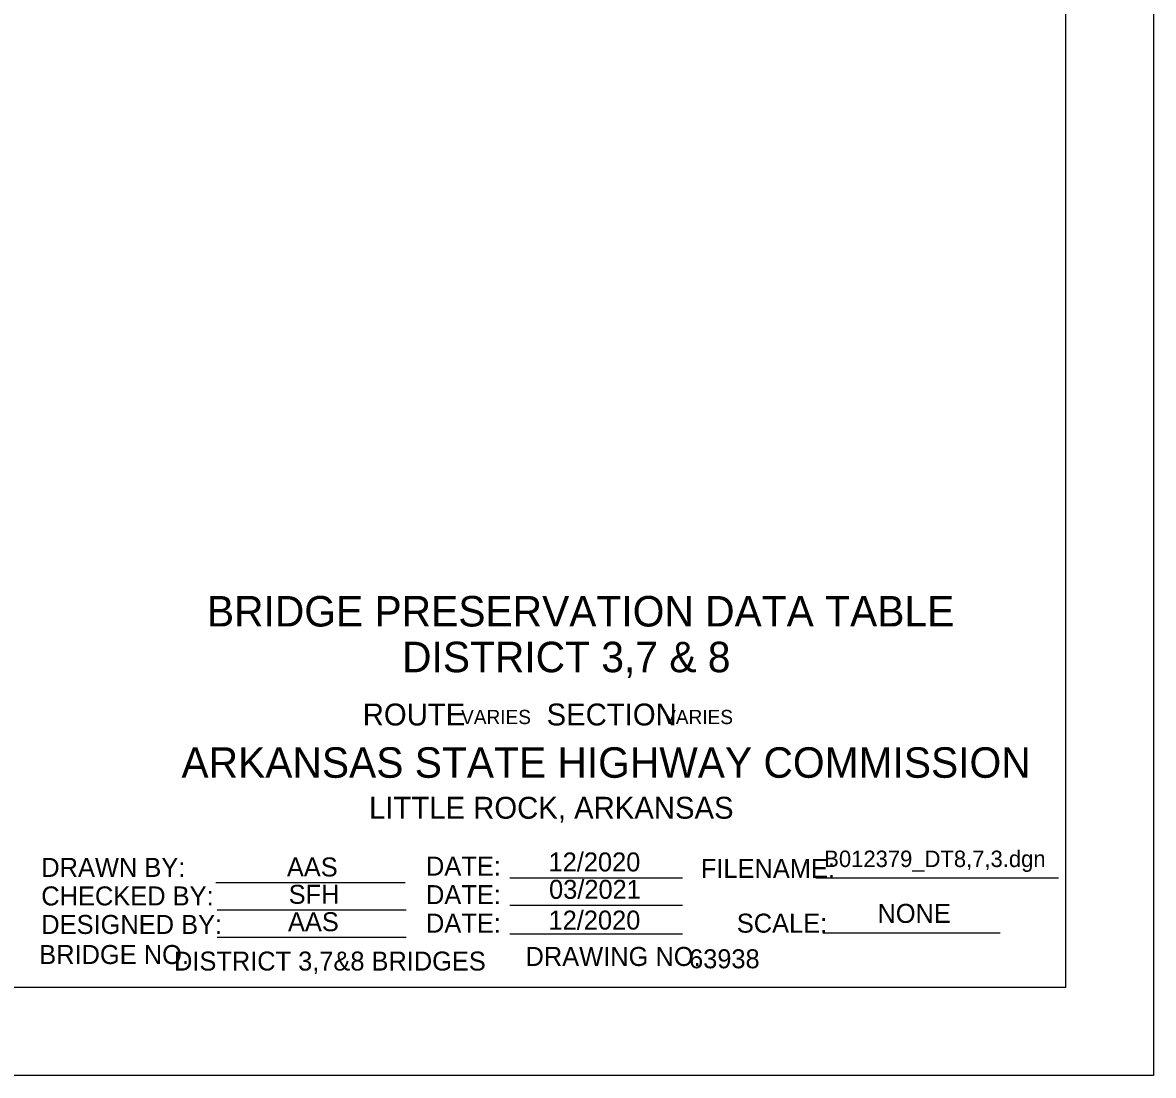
# Model space of a CAD drawing. Extents: x 16 to 1228740, y 11 to 152440.
# Drawn here: x 17.871 to 18.49, y 10.709 to 11.286 of the extents above; entities that cross this region are included whole.
import ezdxf

# ---------------------------------------------------------------- set-up
doc = ezdxf.new("R2010")
doc.units = 0
for name, color, linetype in [('B_Copy In', 7, 'Continuous'), ('B_Text', 7, 'Continuous'), ('B_Title Text', 7, 'Continuous'), ('R_Border', 7, 'Continuous')]:
    doc.layers.add(name, color=color, linetype=linetype)

msp = doc.modelspace()

# ---------------------------------------------------------------- linework, layer by layer
at = {"layer": 'B_Text'}
for p, q in [((17.97661, 10.81515), (18.08021, 10.81515)), ((18.13771, 10.81765), (18.23221, 10.81765)), ((18.30529, 10.81765), (18.43835, 10.81765)), ((17.97721, 10.80015), (18.08081, 10.80015)), ((18.13771, 10.80265), (18.23221, 10.80265)), ((18.13771, 10.80265), (18.23221, 10.80265)), ((18.30917, 10.78765), (18.40631, 10.78765)), ((17.97721, 10.78515), (18.08081, 10.78515)), ((18.13771, 10.78703), (18.23221, 10.78703))]:
    msp.add_line(p, q, dxfattribs=at)
at = {"layer": 'R_Border'}
for q in [(18.44221, 12.49475), (15.78327, 10.75755)]:
    msp.add_line((18.44221, 10.75755), q, dxfattribs=at)
msp.add_lwpolyline([(15.65694, 12.54282), (18.49027, 12.54282), (18.49027, 10.70949), (15.65694, 10.70949)], close=True, dxfattribs=at)

# ---------------------------------------------------------------- texts
at = {"layer": 'B_Copy In'}
for s, height, p in [('BRIDGE PRESERVATION DATA TABLE ', 0.0167, (17.97167, 10.95536)), ('DISTRICT 3,7 & 8', 0.0167, (18.07861, 10.93031)), ('12/2020', 0.0104, (18.15886, 10.82119)), ('B012379_DT8,7,3.dgn', 0.0090123, (18.30993, 10.8236)), ('AAS', 0.0104, (18.0155, 10.81846)), ('SFH', 0.0104, (18.01647, 10.80346)), ('03/2021', 0.0104, (18.15915, 10.80619)), ('12/2020', 0.0104, (18.15886, 10.78934)), ('NONE', 0.0104, (18.3391, 10.79302)), ('AAS', 0.0104, (18.0161, 10.78846)), ('DISTRICT 3,7&8 BRIDGES', 0.0104, (17.95367, 10.7669)), ('63938', 0.0104, (18.23586, 10.76815))]:
    msp.add_text(s, height=height, dxfattribs=at).set_placement(p)
at = {"layer": 'B_Text'}
for s, height, p in [('DRAWN BY:', 0.010417, (17.88091, 10.8182)), ('DATE:', 0.010417, (18.09171, 10.8189)), ('FILENAME:', 0.010417, (18.24229, 10.81765)), ('CHECKED BY:', 0.0104166, (17.88091, 10.80257)), ('DATE:', 0.010417, (18.09171, 10.80328)), ('DESIGNED BY:', 0.0104166, (17.88091, 10.78695)), ('DATE:', 0.010417, (18.09171, 10.78765)), ('SCALE:', 0.010417, (18.26201, 10.78765)), ('BRIDGE NO.', 0.010417, (17.87978, 10.77048)), ('DRAWING NO.', 0.0104166, (18.14623, 10.76942))]:
    msp.add_text(s, height=height, dxfattribs=at).set_placement(p)
at = {"layer": 'B_Title Text'}
for s, height, p in [('ROUTE          SECTION ', 0.012, (18.05705, 10.90115)), ('ROUTE          SECTION ', 0.012, (18.05705, 10.90115)), ('                VARIES                         VARIES', 0.0078, (18.06459, 10.9019)), ('ARKANSAS STATE HIGHWAY COMMISSION', 0.0167, (17.95772, 10.8725)), ('LITTLE ROCK, ARKANSAS', 0.012, (18.0605, 10.85007))]:
    msp.add_text(s, height=height, dxfattribs=at).set_placement(p)

doc.saveas('drawing.dxf')
